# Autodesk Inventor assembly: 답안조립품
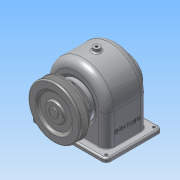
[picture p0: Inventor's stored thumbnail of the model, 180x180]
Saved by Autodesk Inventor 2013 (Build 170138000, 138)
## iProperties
Created: 2016-01
Part Number: 답안조립품
Document SubType Name: Assembly
Designer: Administrator
Author: Administrator
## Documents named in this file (16)
- C:\Users\Administrator\Desktop\460106V1026\답안조립품.iam
- C:\Users\Administrator\Desktop\460106V1026\V-벨트풀리.ipt
- C:\Users\Administrator\Desktop\460106V1026\뒤커버.ipt
- C:\Users\Administrator\Desktop\460106V1026\멈춤나사 - M4x10.ipt
- C:\Users\Administrator\Desktop\460106V1026\베어링 6203.ipt
- C:\Users\Administrator\Desktop\460106V1026\본체.ipt
- C:\Users\Administrator\Desktop\460106V1026\볼트 M3 x 8.ipt
- C:\Users\Administrator\Desktop\460106V1026\볼트 M3 x 10.ipt
- C:\Users\Administrator\Desktop\460106V1026\부시1.ipt
- C:\Users\Administrator\Desktop\460106V1026\부시2.ipt
- C:\Users\Administrator\Desktop\460106V1026\스퍼기어.ipt
- C:\Users\Administrator\Desktop\460106V1026\앞커버.ipt
- C:\Users\Administrator\Desktop\460106V1026\오일씰 28 40 8.ipt
- C:\Users\Administrator\Desktop\460106V1026\축.ipt
- C:\Users\Administrator\Desktop\460106V1026\키 - 5 x 5 x 18.ipt
- C:\Users\Administrator\Desktop\460106V1026\키 - 6 x 6 x 22.ipt
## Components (9 placed, 3 different names)
1. V-벨트풀리:1 — 각도:1
2. ISO 4762 M3 x 8:1
3. ISO 4762 M3 x 8:2
4. ISO 4762 M3 x 8:3
5. ISO 4762 M3 x 8:4
6. ISO 4762 M3 x 10:1
7. ISO 4762 M3 x 10:2
8. ISO 4762 M3 x 10:3
9. ISO 4762 M3 x 10:4
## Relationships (1: Angle 1)
- 각도:1 [Angle]: V-벨트풀리:1
